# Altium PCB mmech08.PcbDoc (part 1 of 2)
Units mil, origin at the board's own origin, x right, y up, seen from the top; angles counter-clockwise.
Board outline 2098.43 x 3200 mil, 4 copper layers (Top Layer, Ground Plane, Mid Layer 1, Bottom Layer), stack 59.851 mil thick; 121 components, 87 nets, 440 pads, 296 vias.
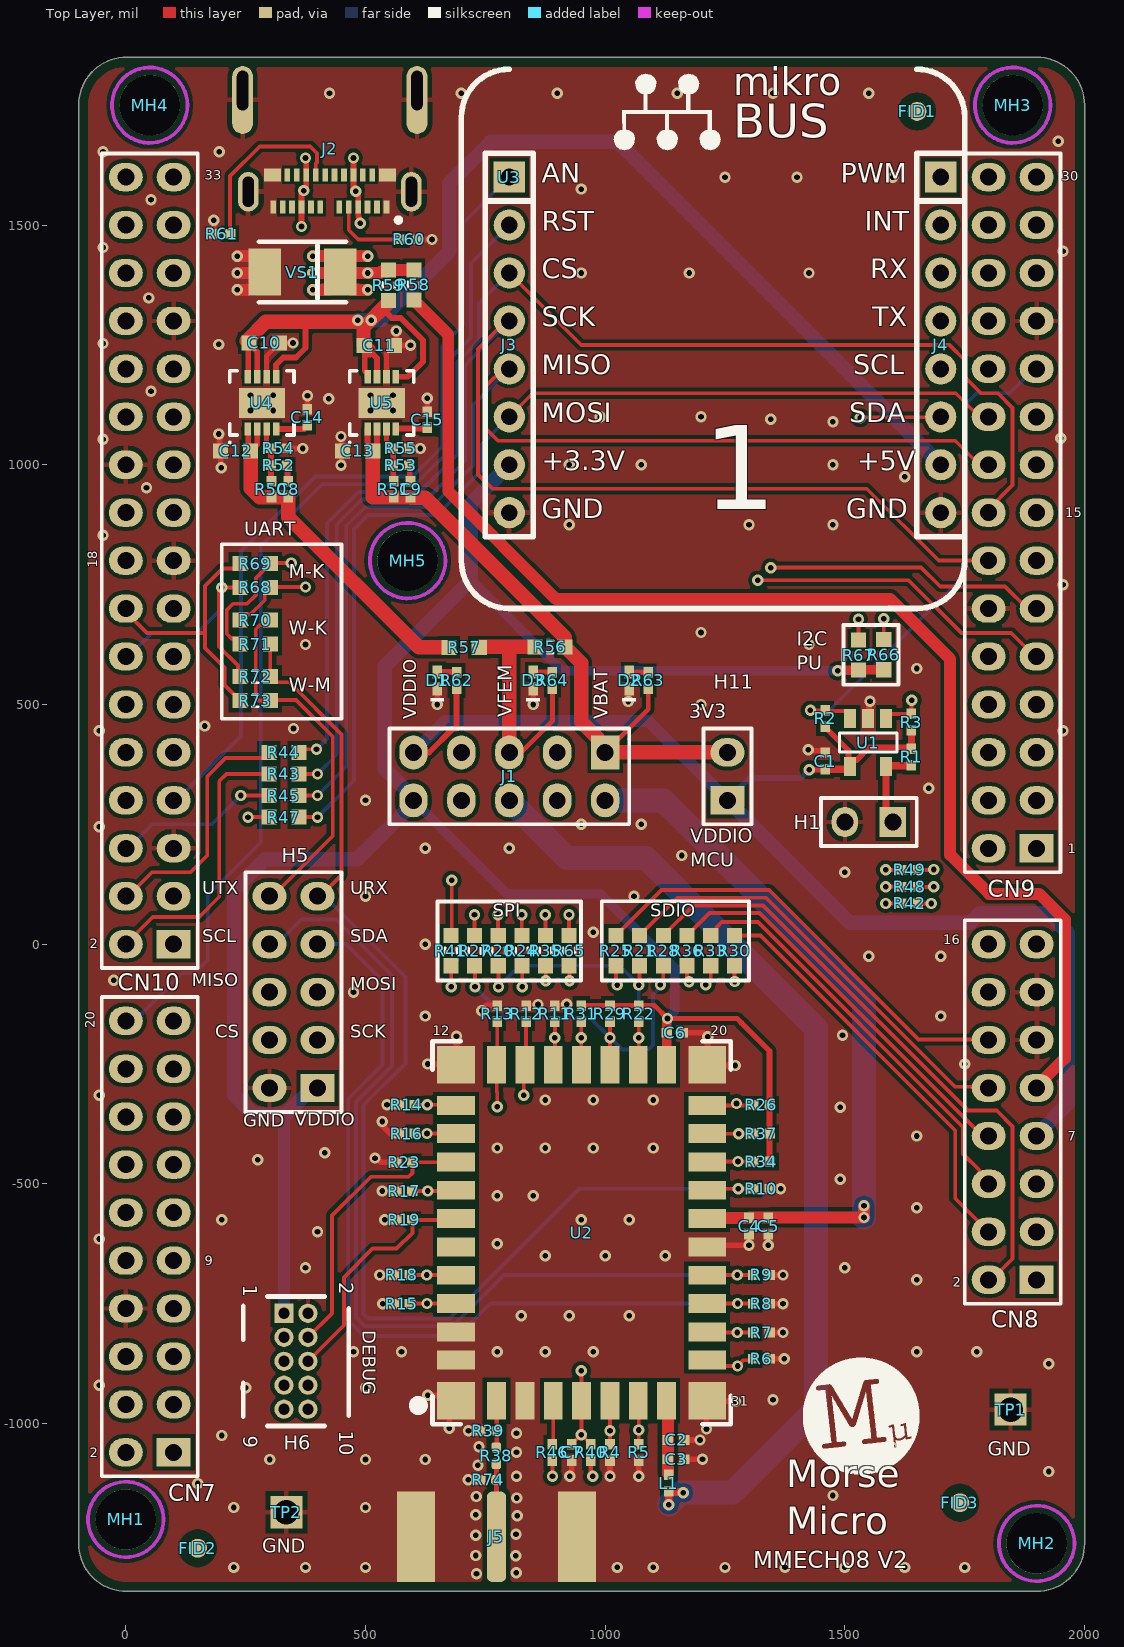
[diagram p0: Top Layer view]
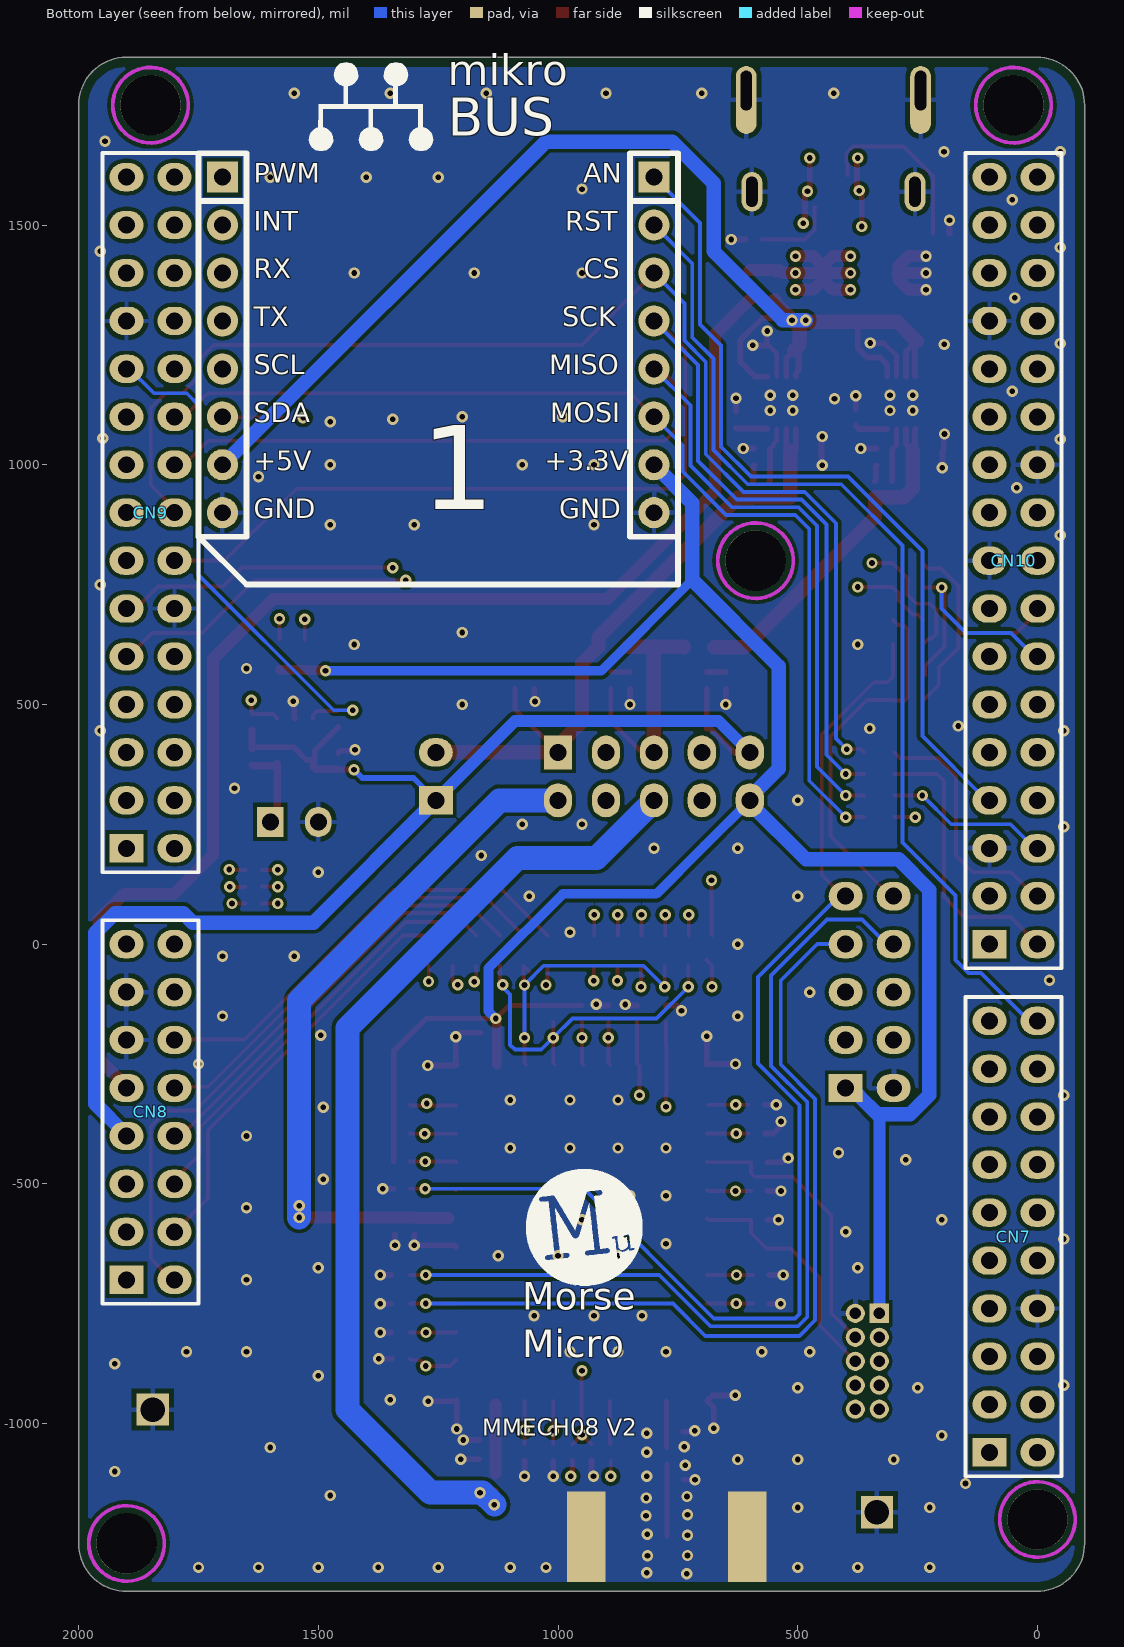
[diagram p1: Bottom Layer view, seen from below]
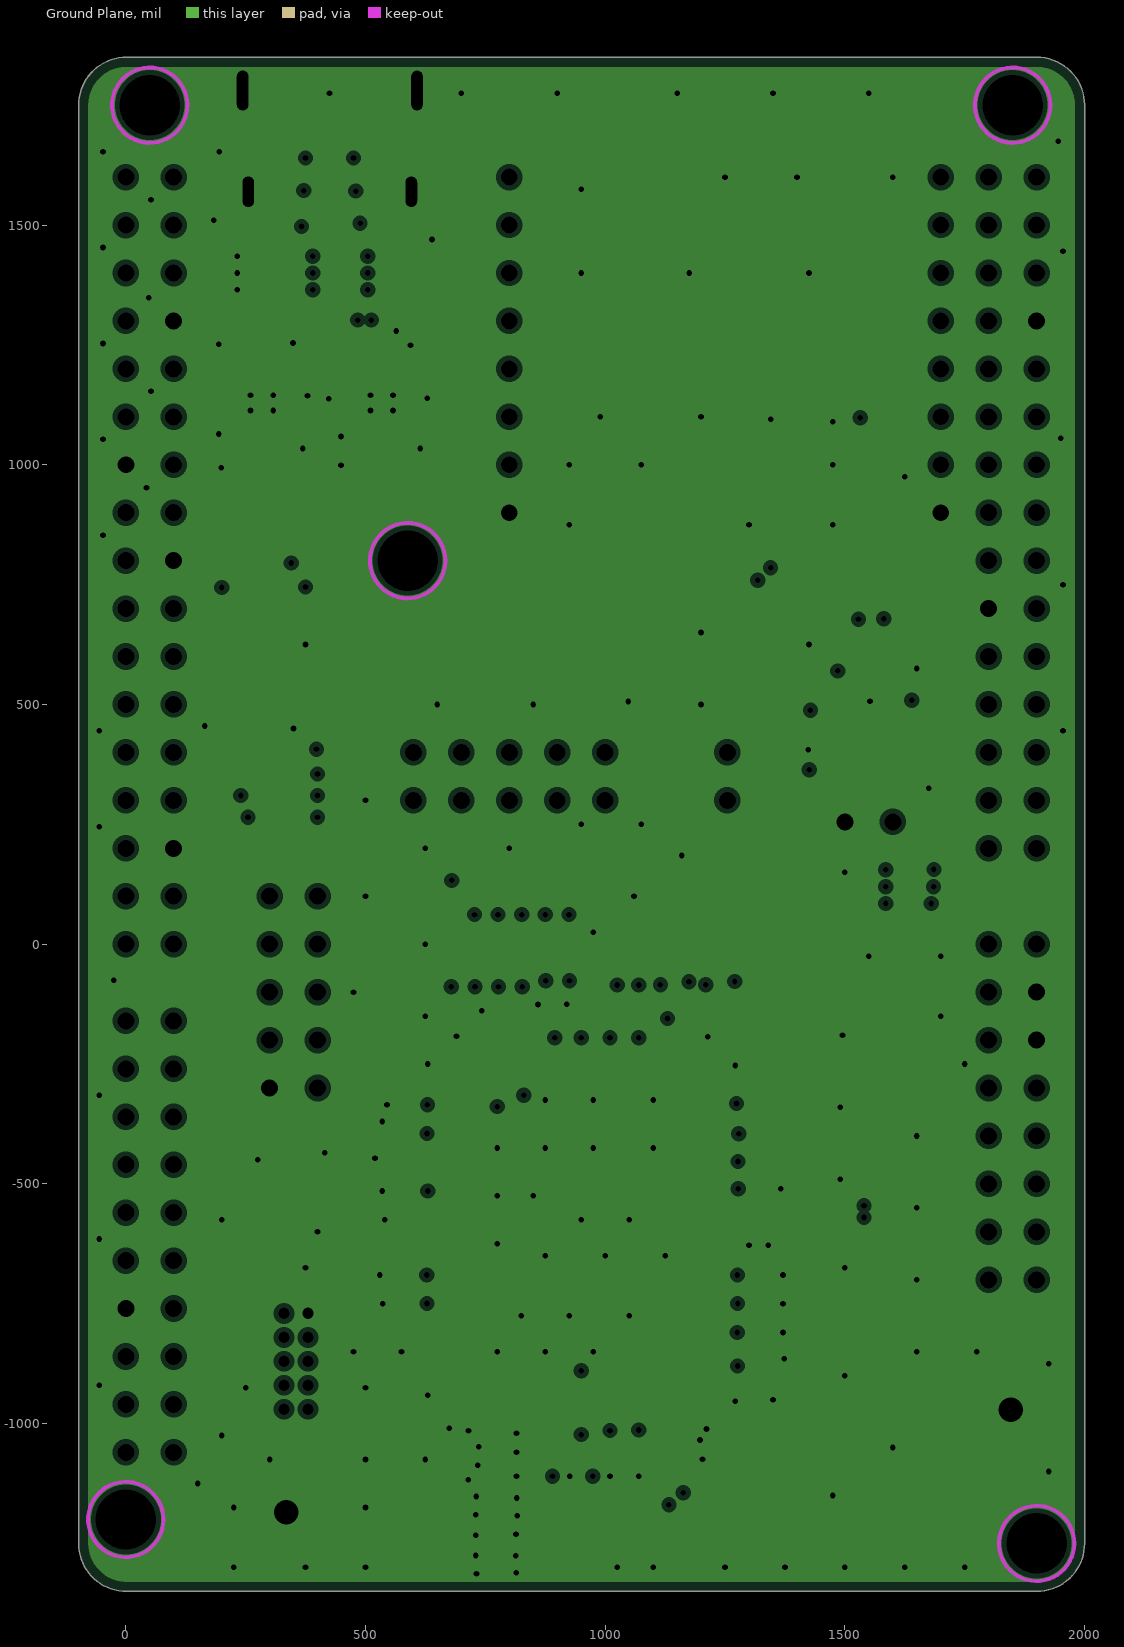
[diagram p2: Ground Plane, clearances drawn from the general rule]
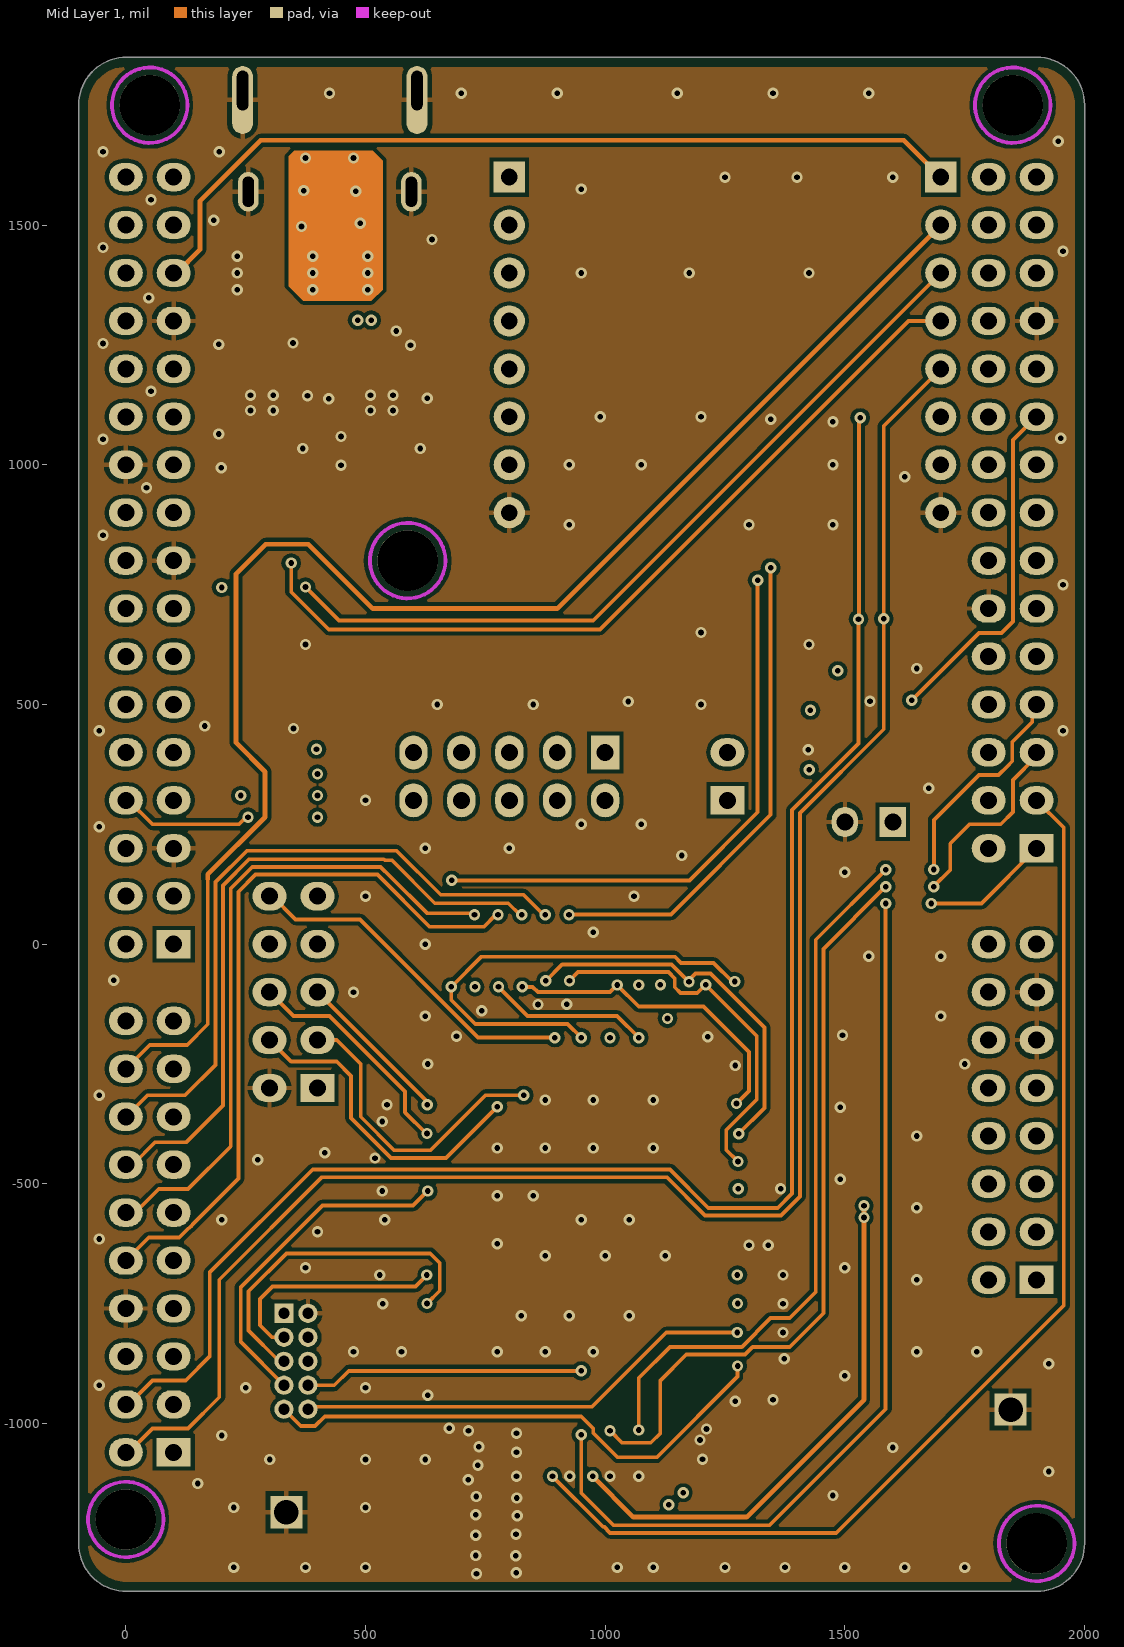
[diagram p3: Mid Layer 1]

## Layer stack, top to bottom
Top Solder: solder mask 0.787, SM-001, Dk 4.2
Top Layer: signal copper 1.378
Dielectric 1: prepreg 6.5, PP, Dk 4.29
Ground Plane: plane copper 1.378, net GND
Dielectric 2: core 41.3386, Core, Dk 4.29
Mid Layer 1: signal copper 1.378
Dielectric 3: prepreg 6.5, PP, Dk 4.29
Bottom Layer: signal copper 1.378
Bottom Solder: solder mask 0.787, SM-001, Dk 4.2

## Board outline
-98.37,-1250 -98.37,1750 cw(c1.63,1750) 1.63,1850 1900.05,1850 cw(c1900.05,1750) 2000.05,1750 2000.05,-1250 2000.02,-1250 cw(c1900.02,-1250) 1900.02,-1350 1.63,-1350 cw(c1.63,-1250)

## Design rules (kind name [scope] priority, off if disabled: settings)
AssemblyTestPointUsage [All] p1 off:
AssemblyTestpoint [All] p1 off: testpointundercomponent=TRUE minsize=40 maxsize=100 preferedsize=60 minholesize=0 maxholesize=40 preferedholesize=32 testpointgrid=1 usegrid=TRUE gridtolerance=0.01 allowsidetop=TRUE allowsidebottom=TRUE
BoardOutlineClearance [(not OnTopSilkscreen) AND (NOT OnBottomSilkscreen) and (not OnMultiLayer) and (not IsText)] p1: gap=20 ignorepadtopadclearanceinfootprint=FALSE
Clearance "RF Clearance" [InNetClass('RF-Net') vs InPolygon] p1: gap=10 ignorepadtopadclearanceinfootprint=TRUE
Clearance "Schematic Clearance Constraint_2" [InComponent('FID3')] p2: gap=0 ignorepadtopadclearanceinfootprint=FALSE
Clearance "Schematic Clearance Constraint_1" [InComponent('FID2')] p3: gap=0 ignorepadtopadclearanceinfootprint=FALSE
Clearance "Schematic Clearance Constraint" [InComponent('FID1')] p4: gap=0 ignorepadtopadclearanceinfootprint=FALSE
Clearance Clearance_U4_U5_J2 [InComponent('J2','U4','U5')] p5: gap=6 ignorepadtopadclearanceinfootprint=TRUE
Clearance [All] p6: gap=8 ignorepadtopadclearanceinfootprint=TRUE
ComponentClearance [All] p1 off: gap=10 collisioncheckmode=3 verticalgap=10 showdistances=FALSE
DiffPairsRouting [All] p1 off: maxlimit=10 minlimit=10 mostfreqgap=10 toplayer_minwidth=15 toplayer_maxwidth=15 toplayer_prefwidth=15 midlayer3_minwidth=15 midlayer3_maxwidth=15 midlayer3_prefwidth=15 bottomlayer_minwidth=15 bottomlayer_maxwidth=15 bottomlayer_prefwidth=15 maxuncoupledlength=500
FabricationTestPointUsage [All] p1 off: valid=0 allowmultiple=FALSE
FabricationTestpoint [All] p1 off: side=3 testpointundercomponent=TRUE minsize=40 maxsize=100 preferedsize=60 minholesize=0 maxholesize=40 preferedholesize=32 testpointgrid=1 allowsidetop=TRUE allowsidebottom=TRUE usegrid=TRUE gridtolerance=0.01
FanoutControl Fanout_BGA [IsBGA] p1 off: bgadir=Out bgaviamode=Centered fanoutstyle=Auto fanoutdirection=Alternating viagrid=1 // Fanout_BGA (Default Rule)
FanoutControl Fanout_LCC [IsLCC] p2 off: bgadir=Out bgaviamode=Centered fanoutstyle=Auto fanoutdirection=Alternating viagrid=1 // Fanout_LCC (Default Rule)
FanoutControl Fanout_SOIC [IsSOIC] p3 off: bgadir=Out bgaviamode=Centered fanoutstyle=Auto fanoutdirection=Alternating viagrid=1 // Fanout_SOIC (Default Rule)
FanoutControl Fanout_Small [(CompPinCount < 5)] p4 off: bgadir=Out bgaviamode=Centered fanoutstyle=Auto fanoutdirection=OutThenIn viagrid=1 // Fanout_Small (Default Rule)
FanoutControl Fanout_Default [All] p5 off: bgadir=Out bgaviamode=Centered fanoutstyle=Auto fanoutdirection=Alternating viagrid=1 // Fanout_Default (Default Rule)
Height TP1 [InComponent('TP1')] p1: minheight=0 maxheight=472.44 prefheight=118.11
Height "POGO Pins" [InComponentClass('POGO')] p2: minheight=0 maxheight=275.59 prefheight=196.85
Height "Under Socket" [WithinRoom('ROOM_SOCKET')] p3: minheight=0 maxheight=157.48 prefheight=118.11
Height [All] p4 off: minheight=0 maxheight=1000 prefheight=500
HoleSize [All] p1: absolutevalues=TRUE maxlimit=200 minlimit=8 maxpercent=80.000 minpercent=20.000
HoleToHoleClearance [All] p1: gap=8 allowstackedmicrovias=TRUE
LayerPairs [All] p1 off: enforce=TRUE
MatchedLengths MatchLengths_U1_Passives_J5_1 [InxSignalClass('xSignals_U1_Passives_J5_MatchLengthsClass_1')] p1: tolerance=50 checknetsindiffpair=FALSE checkdiffpairvsdiffpair=TRUE checkxsignals=TRUE checkothers=TRUE
MatchedLengths MatchLengths_U1_Passives_J5 [InxSignalClass('xSignals_U1_Passives_J5_MatchLengthsClass')] p2: tolerance=50 checknetsindiffpair=FALSE checkdiffpairvsdiffpair=TRUE checkxsignals=TRUE checkothers=TRUE
MinimumSolderMaskSliver [not InComponent('U4','U1','U5','U6','U7','U8','U9','U10')] p1: minsoldermaskwidth=3
PlaneClearance [All] p1: clearance=10
PlaneConnect [All] p1: pad.planeconnectstyle=Relief pad.reliefexpansion=20 pad.reliefentries=4 pad.reliefconductorwidth=10 pad.reliefairgap=10 via.planeconnectstyle=Direct via.reliefexpansion=20 via.reliefentries=4 via.reliefconductorwidth=10 via.reliefairgap=10
PolygonConnect "Schematic Polygon Connect Style" [InComponent('J5')] p1: connectstyle=Direct reliefconductorwidth=10 reliefentries=4 polygonreliefangle="45 Angle" airgapwidth=10
PolygonConnect [All] p2: thpad.connectstyle=Relief thpad.reliefconductorwidth=10 thpad.reliefentries=4 thpad.polygonreliefangle="90 Angle" thpad.airgapwidth=10 smdpad.connectstyle=Direct smdpad.reliefconductorwidth=10 smdpad.reliefentries=4 smdpad.polygonreliefangle="90 Angle" smdpad.airgapwidth=10 via.connectstyle=Direct via.reliefconductorwidth=10 via.reliefentries=4 via.polygonreliefangle="90 Angle" via.airgapwidth=10
RoutingVias [All] p1: holewidth=8 width=20 viastyle="Through Hole" minholewidth=8 minwidth=20 maxholewidth=28 maxwidth=50
SilkToSilkClearance [All] p1 off: silktosilkclearance=8
SilkToSolderMaskClearance [IsPad] p1 off: minsilkscreentomaskgap=4 clearancetoexposedcopper=TRUE
SolderMaskExpansion [All] p1: expansion=4 istentingtop=FALSE
SupplyNets SupplyNets_1 [InNet('VDD33')] p1: voltage=3.300
SupplyNets SupplyNets_2 [InNet('VBAT')] p2: voltage=3.300
SupplyNets SupplyNets_3 [InNet('VDD5')] p3: voltage=5.000
SupplyNets SupplyNets_4 [InNet('VDD5_RPi')] p4: voltage=5.000
SupplyNets SupplyNets_5 [InNet('VDD_FEM')] p5: voltage=4.000
SupplyNets SupplyNets_6 [InNet('VDD_LNA')] p6: voltage=4.000
SupplyNets SupplyNets_7 [InNet('VDD_PA')] p7: voltage=4.000
SupplyNets [InNet('GND')] p8: voltage=0.000
UnConnectedPin [All] p1 off:
UnRoutedNet [All] p1: checkbadconnections=TRUE
Width [All] p1: maxlimit=50 minlimit=8 preferedwidth=8
Width "RF Width" [InNetClass('RF-Net')] p2: maxlimit=50 minlimit=7 preferedwidth=8 toplayer_maxwidth=7 toplayer_prefwidth=10 impedanceprofiledriven=TRUE impedanceprofileid={2BAD1660-FF1E-4629-AB45-93BC2CD73358} impedanceprofilevalue=50.000000 minimp=50.000000 maximp=50.000000 favimp=50.000000
9 further rules are at their usual default settings.

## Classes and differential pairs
net class RF-Net: NetJ5_1 NetR38_1
component class CHIP_OTHER: C10 C11 C12 C13 D1 D2 D3 R20 R21 R24 R25 R27 R28 R30 R33 R35 R36 R41 R43 R44 R45 R47 R56 R57 R58 R59 R65 R66 R67 R68 R69 R70 R71 R72 R73
component class MMECH08_Power: C8 C9 C10 C11 C12 C13 C14 C15 D1 D2 D3 FID1 FID2 FID3 H11 J1 J2 MH1 MH2 MH3 MH4 MH5 R50 R51 R52 R53 R54 R55 R56 R57 R58 R59 R60 R61 R62 R63 R64 TP1 TP2 U4 U5 VS1
component class CHIP_MICRO: C1 C2 C3 C4 C5 C6 C7 C8 C9 C14 C15 L1 R1 R2 R3 R4 R5 R6 R7 R8 R9 R10 R11 R12 R13 R14 R15 R16 R17 R18 R19 R22 R23 R26 R29 R31 R34 R37 R38 R39 R40 R42 R46 R48 R49 R50 R51 R52 R53 R54 R55 R60 R61 R62 R63 R64 R74
component class MMECH08_Module_Interfaces: C1 C2 C3 C4 C5 C6 C7 CN7 CN8 CN9 CN10 H1 H5 H6 J3 J4 J5 L1 R1 R2 R3 R4 R5 R6 R7 R8 R9 R10 R11 R12 R13 R14 R15 R16 R17 R18 R19 R20 R21 R22 R23 R24 R25 R26 R27 R28 R29 R30 R31 R33 R34 R35 R36 R37 R38 R39 R40 R41 R42 R43 R44 R45 R46 R47 R48 R49 R65 R66 R67 R68 R69 R70 R71 R72 R73 R74 U1 U2 U3
component class PCB_PATTERN: FID1 FID2 FID3 FID7 FID8 MH1 MH2 MH3 MH4 MH5
component class COMP_OTHER: CN7 CN8 CN9 CN10 H1 H5 H6 H11 J1 J2 J3 J4 J5 TP1 TP2 U1 U2 U3 U4 U5 VS1

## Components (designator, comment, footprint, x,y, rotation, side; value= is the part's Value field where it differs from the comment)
C1 "CAP" 0402_CAP 1458.63,382 r90 top value=100nF
C2 "CAP" 0402_CAP 1147.84,-1034.16 r0 top value=100nF
C3 "CAP" 0402_CAP 1147.84,-1074.16 r0 top value=10uF
C4 "CAP" 0402_CAP 1300,-588 r90 top value=100nF
C5 "CAP" 0402_CAP 1340,-588 r270 top value=10uF
C6 "CAP" 0402_CAP 1145,-185 r0 top value=100nF
C7 "CAP" 0402_CAP 930,-1060 r270 top value=2.2uF
C8 "CAP_DNF" 0402_cap_dnf 338.94,949 r90 top value=DNF
C9 "CAP_DNF" 0402_cap_dnf 593.94,949 r90 top value=DNF
C10 "CAP" 0603_cap 288.94,1254 r0 top value=10uF
C11 "CAP" 0603_cap 528.88,1249 r0 top value=10uF
C12 "CAP" 0603_cap 228.94,1029 r180 top value=10uF
C13 "CAP" 0603_cap 483.94,1029 r180 top value=10uF
C14 "CAP" 0402_cap 378.94,1099 r90 top value=1nF
C15 "CAP" 0402_cap 628.95,1094 r90 top value=1nF
CN7 ".Designator" HDR2X10 100,-1060 r90 bottom
CN8 ".Designator" HDR2X8 1900,-700 r90 bottom
CN9 ".Designator" HDR2X15 1900,200 r90 bottom
CN10 ".Designator" HDR2X17 100,0 r90 bottom
D1 "LED_G" LED_0402_GREEN 650,550 r270 top value=Green
D2 "LED_G" LED_0402_GREEN 1050,550 r270 top value=Green
D3 "LED_G" LED_0402_GREEN 850,550 r270 top value=Green
FID1 "FIDUCIAL" FIDUCIAL_1MM 1650.63,1737 r0 top
FID2 "FIDUCIAL" FIDUCIAL_1MM 150,-1260 r0 top
FID3 "FIDUCIAL" FIDUCIAL_1MM 1740,-1165 r90 top
H1 "HDR_1X2_DNF" HDR1X2_DNF 1600,255 r180 top
H5 "HDR_2X5" HDR2X5 400,-300 r90 top
H6 "2X5_FTSH_DV_K" FTSH_105_D_K 355,-870 r270 top
H11 "HDR_1X2" HDR1X2 1255,300 r90 top
J1 "HDR_2X5" HDR2X5 1000,400 r180 top
J2 "CONN RCP USB3.1 TYPEC 24P SMD RA" USB-C_RCP 425.63,1659 r180 top
J3 "75915-308LF * 2" 75915-308LF 800,1600 r0 top
J4 "75915-308LF" 75915-308LF 1700,1600 r0 top
J5 "SMA-EDGE" SMA_RA-EDGE 773.27,-1350 r0 top
L1 "IND" 0402_ind 1132.84,-1124.16 r270 top value="60 Ohms @ 100MHz"
MH1 "MH_360_320_NPTH" MH_360_320_NPTH 0.02,-1200 r0 top locked
MH2 "MH_360_320_NPTH" MH_360_320_NPTH 1900.02,-1250 r0 top locked
MH3 "MH_360_320_NPTH" MH_360_320_NPTH 1850.02,1750 r0 top locked
MH4 "MH_360_320_NPTH" MH_360_320_NPTH 50.02,1750 r0 top locked
MH5 "MH_360_320_NPTH" MH_360_320_NPTH 588.02,800 r0 top locked
R1 "RES" 0402_RES#1 1638.63,390.63 r270 top value=1K
R2 "RES" 0402_RES#1 1458.63,471 r90 top value=3k9
R3 "RES" 0402_RES#1 1638.63,463.16 r90 top value=3k9
R4 "RES" 0402_RES#1 1010,-1060 r270 top value=10K
R5 "RES" 0402_res 1070,-1060 r270 top value=10K
R6 "RES" 0402_RES#1 1325.84,-865 r0 top value=10K
R7 "RES" 0402_RES#1 1325.84,-810 r0 top value=10K
R8 "RES" 0402_RES#1 1325.84,-750 r0 top value=10K
R9 "RES" 0402_RES#1 1325.84,-690 r0 top value=10K
R10 "RES" 0402_RES#1 1325.84,-510 r0 top value=10K
R11 "RES" 0402_RES#1 895,-145 r90 top value=10K
R12 "RES" 0402_RES#1 835,-145 r90 top value=10K
R13 "RES" 0402_RES#1 775,-145 r90 top value=10K
R14 "RES" 0402_RES#1 585.84,-335 r180 top value=10K
R15 "RES" 0402_RES#1 575.84,-750 r180 top value=10K
R16 "RES" 0402_RES#1 585.84,-395 r180 top value=10K
R17 "RES_DNF" 0402_res_dnf#1 580.84,-515 r180 top value=DNF
R18 "RES" 0402_RES#1 575.84,-690 r180 top value=10K
R19 "RES" 0402_RES#1 580.84,-575 r180 top value=10K
R20 "RES" 0603_res 776.91,-13.5 r270 top value=0R
R21 "RES_DNF" 0603_res_dnf 1071.75,-13.5 r90 top value=DNF
R22 "RES" 0402_RES#1 1070,-145 r270 top value=47k
R23 "RES" 0402_RES#1 580.84,-455 r180 top value=10K
R24 "RES" 0603_res 826.2,-13.5 r270 top value=0R
R25 "RES_DNF" 0603_res_dnf 1022.28,-13.5 r90 top value=DNF
R26 "RES" 0402_RES#1 1325.84,-335 r180 top value=47k
R27 "RES" 0603_res 727.61,-13.5 r270 top value=0R
R28 "RES_DNF" 0603_res_dnf 1121.22,-13.5 r90 top value=DNF
R29 "RES" 0402_RES#1 1010,-145 r90 top value=47k
R30 "RES_DNF" 0603_res_dnf 1269.63,-13.5 r90 top value=DNF
R31 "RES" 0402_RES#1 950,-145 r90 top value=47k
R33 "RES_DNF" 0603_res_dnf 1220.16,-13.5 r90 top value=DNF
R34 "RES" 0402_RES#1 1325.84,-453.39 r0 top value=47k
R35 "RES" 0603_res 875.5,-13.5 r270 top value=0R
R36 "RES_DNF" 0603_res_dnf 1170.69,-13.5 r90 top value=DNF
R37 "RES" 0402_RES#1 1325.84,-395 r180 top value=47k
R38 "RES" 0402_RES#2 773,-1067 r270 top value=0R
R39 "RES_DNF" 0402_res_dnf#2 756.13,-1015.12 r180 top value=DNF
R40 "RES" 0402_RES#1 970,-1060 r90 top value=220k
R41 "RES" 0603_res 678.32,-13.5 r270 top value=0R
R42 "RES" 0402_res 1635,85 r0 top value=0R
R43 "RES_DNF" 0603_res_dnf 330,355 r0 top value=DNF
R44 "RES_DNF" 0603_res_dnf 330,400 r0 top value=DNF
R45 "RES_DNF" 0603_res_dnf 330,310 r0 top value=DNF
R46 "RES" 0402_res 890,-1060 r270 top value=10K
R47 "RES_DNF" 0603_res_dnf 330,265 r0 top value=DNF
R48 "RES" 0402_res 1635,120 r0 top value=0R
R49 "RES" 0402_res 1635,155 r0 top value=0R
R50 "RES" 0402_res 303.94,949 r90 top value=1k
R51 "RES" 0402_res 558.94,949 r90 top value=1k
R52 "RES_DNF" 0402_res_dnf#1 318.94,999 r0 top value=DNF
R53 "RES_DNF" 0402_res_dnf#1 573.94,999 r0 top value=DNF
R54 "RES" 0402_res 318.94,1034 r0 top value=10k
R55 "RES" 0402_res 573.94,1034 r0 top value=10k
R56 "RES" 0603_res 885,620 r180 top value=0R
R57 "RES_DNF" 0603_res_dnf 705.75,619.17 r0 top value=DNF
R58 "RES" 0603_res 600.83,1375.09 r270 top value=0R
R59 "RES" 0603_res 548.29,1374.35 r270 top value=0R
R60 "RES" 0402_RES#1 591.63,1470 r0 top value=5K1
R61 "RES" 0402_RES#1 200.63,1482 r180 top value=5K1
R62 "RES" 0402_RES#1 690,550 r270 top value=330R
R63 "RES" 0402_RES#1 1090,550 r270 top value=330R
R64 "RES" 0402_res 890,550 r270 top value=330R
R65 "RES" 0603_res 924.79,-13.5 r270 top value=0R
R66 "RES_DNF" 0603_res_dnf 1581,604 r90 top value=DNF
R67 "RES_DNF" 0603_res_dnf 1528.47,603.07 r90 top value=DNF
R68 "RES_DNF" 0603_res_dnf 270,744 r180 top value=DNF
R69 "RES_DNF" 0603_res_dnf 270,794 r180 top value=DNF
R70 "RES_DNF" 0603_res_dnf 270,676 r0 top value=DNF
R71 "RES_DNF" 0603_res_dnf 270,626 r0 top value=DNF
R72 "RES" 0603_res 270,558 r0 top value=0R
R73 "RES" 0603_res 270,508 r0 top value=0R
R74 "RES_DNF" 0402_res_dnf#2 756.13,-1117.12 r180 top value=DNF
TP1 "TP-BLK" TP-100_BLACK 1845.47,-970.93 r0 top
TP2 "TP-BLK" TP-100_BLACK 335,-1185 r0 top
U1 "AT24C32D" SOT-23_5 1548.63,420.63 r270 top
U2 "MM61xx-MF04151" MF04 950.84,-601.97 r90 top locked
U3 "MIKROBUS_Host" MIKROBUS_Host_SD 800,1600 r0 top value="MIKROBUS Host"
U4 "ADM7172" PSON50P300X80_HS-9N 283.94,1129 r90 top
U5 "ADM7172" PSON50P300X80_HS-9N 533.94,1129 r90 top
VS1 "Varistor_Uni" DO-214AC 368.63,1402 r0 top value=6V

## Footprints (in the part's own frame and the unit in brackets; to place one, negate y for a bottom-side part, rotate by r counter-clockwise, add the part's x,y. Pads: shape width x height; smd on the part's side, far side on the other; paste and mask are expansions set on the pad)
0402_CAP [mil]
  rect 22x20 smd: 1(-17,0) 2(17,0)
  body extent -21,-11 21,11, height 22
0402_cap [mil]
  rect 22x20 smd: 1(-17,0) 2(17,0)
  body extent -21,-11 21,11, height 22
0402_cap_dnf [mil]
  rect 22x20 smd paste-196.85: 1(-17,0) 2(17,0)
  body extent -20,-10 20,10, height 20
0402_ind [mil]
  rect 22x20 smd: 1(-17,0) 2(17,0)
  body extent -22,-12 22,12, height 20
0402_RES#1 [mil]
  rect 22x20 smd: 1(-17,0) 2(17,0)
  body extent -21,-11 21,11, height 16
0402_RES#2 [mil]
  rrect50% 22x20 smd: 1(-17,0) 2(17,0)
  body extent -21,-11 21,11, height 16
0402_res [mil]
  rect 22x20 smd: 1(-17,0) 2(17,0)
  body extent -21,-11 21,11, height 16
0402_res_dnf#1 [mil]
  rect 22x20 smd paste-196.85: 1(-17,0) 2(17,0)
  body extent -20,-10 20,10, height 20
0402_res_dnf#2 [mil]
  rrect50% 22x20 smd paste-196.85: 1(-17,0)
  rect 22x20 smd paste-196.85: 2(17,0)
  body extent -20,-10 20,10, height 20
0603_cap [mm]
  rect 0.8x0.8 smd: 1(-0.8,0) 2(0.8,0)
  body extent -0.85,-0.45 0.85,0.45, height 0.9
0603_res [mm]
  rect 0.8x0.8 smd: 1(-0.8,0) 2(0.8,0)
  silkscreen extent -0.15,-0.33 0.15,0.33, body extent -0.82,-0.48 0.82,0.48, height 0.55
0603_res_dnf [mm]
  rect 0.8x0.8 smd paste-10: 1(-0.8,0) 2(0.8,0)
  body extent -0.8,-0.4 0.8,0.4, height 0
75915-308LF [mil] "CONN RCPT 8POS 0.1 GOLD PCB"
  rect 65x65 hole 35: 1(0,0)
  round 65 hole 35: 2(0,-100) 3(0,-200) 4(0,-300) 5(0,-400) 6(0,-500) 7(0,-600) 8(0,-700)
  silkscreen extent -50,-750 50,50, body extent -49,-755 49,55, height 335
DO-214AC [mm]
  rect 1.7x2.5 smd: A(-2,0) K(2,0)
  silkscreen extent -2.3,-1.6 2.3,1.6, body extent -2.6,-1.4 2.6,1.4, height 2.3
FIDUCIAL_1MM [mm]
  round 1 smd paste-1 mask+0.5: 1(0,0)
  Top Layer pour cut-out: -1,0 -0.924,-0.383 -0.707,-0.707 -0.383,-0.924 0,-1 0,-1 0.383,-0.924 0.707,-0.707 0.924,-0.383 1,0 1,0 0.924,0.383 0.707,0.707 0.383,0.924 0,1 0,1 -0.383,0.924 -0.707,0.707 -0.924,0.383 -1,0
FTSH_105_D_K [mil]
  rect 40x40 hole 23.62 mask+3: 1(-100,-25)
  round 40 hole 23.62 mask+3: 2(-100,25) 3(-50,-25) 4(-50,25) 5(0,-25) 6(0,25) 7(50,-25) 8(50,25) 9(100,-25) 10(100,25)
  silkscreen extent -135,-110 135,110, body extent -124,-100 123,100, height 225
HDR1X2 [mm] "Connector; Header; 2 Position"
  rect 1.5x1.8 hole 0.9: 1(0,0)
  oval 1.5x1.8 hole 0.9: 2(2.54,0)
  silkscreen extent -1.27,-1.27 3.81,1.27, body extent -1.27,-1.22 3.81,1.22, height 10.3
HDR1X2_DNF [mm] "Connector; Header; 2 Position"
  rect 1.4x1.6 hole 0.9: 1(0,0)
  oval 1.4x1.6 hole 0.9: 2(2.54,0)
  silkscreen extent -1.27,-1.27 3.81,1.27, body extent -1.27,-1.27 3.81,1.27, height 0.01
HDR2X5 [mm] "Connector; Header; 5x2 Position"
  rect 1.5x1.8 hole 0.9: 1(0,0)
  oval 1.5x1.8 hole 0.9: 2(0,2.54) 3(2.54,0) 4(2.54,2.54) 5(5.08,0) 6(5.08,2.54) 7(7.62,0) 8(7.62,2.54) 9(10.16,0) 10(10.16,2.54)
  silkscreen extent -1.27,-1.27 11.43,3.81, body extent -1.27,-1.27 11.43,3.81, height 9
HDR2X8 [mm] "Connector; Header; 8x2 Position"
  rect 1.5x1.8 hole 0.9: 1(0,0)
  oval 1.5x1.8 hole 0.9: 2(0,-2.54) 3(2.54,0) 4(2.54,-2.54) 5(5.08,0) 6(5.08,-2.54) 7(7.62,0) 8(7.62,-2.54) 9(10.16,0) 10(10.16,-2.54) 11(12.7,0) 12(12.7,-2.54) 13(15.24,0) 14(15.24,-2.54) 15(17.78,0) 16(17.78,-2.54)
  silkscreen extent -1.27,-3.81 19.05,1.27, body extent -1.27,-3.81 19.05,1.27, height 9
HDR2X10 [mm] "Connector; Header; 10x2 Position"
  rect 1.5x1.8 hole 0.9: 1(0,0)
  oval 1.5x1.8 hole 0.9: 2(0,-2.54) 3(2.54,0) 4(2.54,-2.54) 5(5.08,0) 6(5.08,-2.54) 7(7.62,0) 8(7.62,-2.54) 9(10.16,0) 10(10.16,-2.54) 11(12.7,0) 12(12.7,-2.54) 13(15.24,0) 14(15.24,-2.54) 15(17.78,0) 16(17.78,-2.54) 17(20.32,0) 18(20.32,-2.54) 19(22.86,0) 20(22.86,-2.54)
  silkscreen extent -1.27,-3.81 24.13,1.27, body extent -1.27,-3.81 24.13,1.27, height 9
HDR2X15 [mm] "Connector; Header; 15x2 Position"
  rect 1.5x1.8 hole 0.9: 1(0,0)
  oval 1.5x1.8 hole 0.9: 2(0,-2.54) 3(2.54,0) 4(2.54,-2.54) 5(5.08,0) 6(5.08,-2.54) 7(7.62,0) 8(7.62,-2.54) 9(10.16,0) 10(10.16,-2.54) 11(12.7,0) 12(12.7,-2.54) 13(15.24,0) 14(15.24,-2.54) 15(17.78,0) 16(17.78,-2.54) 17(20.32,0) 18(20.32,-2.54) 19(22.86,0) 20(22.86,-2.54) 21(25.4,0) 22(25.4,-2.54) 23(27.94,0) 24(27.94,-2.54) 25(30.48,0) 26(30.48,-2.54) 27(33.02,0) 28(33.02,-2.54) 29(35.56,0) 30(35.56,-2.54)
  silkscreen extent -1.27,-3.81 36.83,1.27, body extent -1.27,-3.81 36.83,1.27, height 9
HDR2X17 [mm] "Connector; Header; 17x2 Position"
  rect 1.5x1.8 hole 0.9: 1(0,0)
  oval 1.5x1.8 hole 0.9: 2(0,-2.54) 3(2.54,0) 4(2.54,-2.54) 5(5.08,0) 6(5.08,-2.54) 7(7.62,0) 8(7.62,-2.54) 9(10.16,0) 10(10.16,-2.54) 11(12.7,0) 12(12.7,-2.54) 13(15.24,0) 14(15.24,-2.54) 15(17.78,0) 16(17.78,-2.54) 17(20.32,0) 18(20.32,-2.54) 19(22.86,0) 20(22.86,-2.54) 21(25.4,0) 22(25.4,-2.54) 23(27.94,0) 24(27.94,-2.54) 25(30.48,0) 26(30.48,-2.54) 27(33.02,0) 28(33.02,-2.54) 29(35.56,0) 30(35.56,-2.54) 31(38.1,0) 32(38.1,-2.54) 33(40.64,0) 34(40.64,-2.54)
  silkscreen extent -1.27,-3.81 41.91,1.27, body extent -1.27,-3.81 41.91,1.27, height 9
LED_0402_GREEN [mm]
  rect 0.7x0.5 smd: A(-0.45,0) K(0.45,0)
  silkscreen extent 0.93,-0.38 1.1,0.35, body extent -0.5,-0.25 0.5,0.25, height 0.51
MF04 [mm]
  rect 2x2 smd: 1(-8.9,6.65) 12(8.9,6.65) 20(8.9,-6.65) 31(-8.9,-6.65)
  rect 1x2 smd: 2(-6.75,6.65) 3(-5.25,6.65) 4(-3.75,6.65) 5(-2.25,6.65) 6(-0.75,6.65) 7(0.75,6.65) 8(2.25,6.65) 9(3.75,6.65) 10(5.25,6.65) 11(6.75,6.65) 21(6.75,-6.65) 22(5.25,-6.65) 23(3.75,-6.65) 24(2.25,-6.65) 25(0.75,-6.65) 26(-0.75,-6.65) 27(-2.25,-6.65) 28(-3.75,-6.65) 29(-5.25,-6.65) 30(-6.75,-6.65)
  rect 2x1 smd: 13(8.9,4.5) 14(8.9,3) 15(8.9,1.5) 16(8.9,0) 17(8.9,-1.5) 18(8.9,-3) 19(8.9,-4.5) 32(-8.9,-4.5) 33(-8.9,-3) 34(-8.9,-1.5) 35(-8.9,0) 36(-8.9,1.5) 37(-8.9,3) 38(-8.9,4.5)
  silkscreen extent -10.15,-7.9 10.15,8.9, body extent -9.25,-7 9.25,7, height 1.9
MH_360_320_NPTH [mm] "Non-plated mount hole 3.2mm hole 3.60mm diameter"
  round 3.2 hole 3.2 unplated mask+0.25: 1(0,0)
  Keep-Out Layer circle w0.2: c0,0 r2
MIKROBUS_Host_SD [mil] "MIKROBUS HOST SOCKET"
  silkscreen extent -100,-900 950,225, body extent -49,-755 949,55, height 335
PSON50P300X80_HS-9N [mm] "PSON, 8-Leads, Body 3.00x3.00mm, Pitch 0.50mm, Thermal Pad 2.44x1.60mm, IPC Medium Density"
  rect 0.7x0.35 smd mask+0.076: 1(-1.385,0.75) 2(-1.385,0.25) 3(-1.385,-0.25) 4(-1.385,-0.75) 5(1.385,-0.75) 6(1.385,-0.25) 7(1.385,0.25) 8(1.385,0.75)
  rect 1.6x2.44 smd mask+0.076: EP(0,0)
  silkscreen extent -2.15,-1.7 1.7,1.75, body extent -1.55,-1.55 1.55,1.55, height 0.8
SMA_RA-EDGE [mil]
  rrect50% 39.37x188 smd: 1(0,114)
  rect 80x188 smd: 2(-168,114) 2(168,114)
  rect 80x188 smd far side: 2(-168,114) 2(168,114)
  body extent -188,-375 187,187, height 172
SOT-23_5 [mil]
  rect 39x25 smd: 1(-50,37.5) 2(-50,0) 3(-50,-37.5) 4(50,-37.5) 5(50,37.5)
  silkscreen extent -20,-60 20,60, body extent -52,-60 51,60, height 39
TP-100_BLACK [mm]
  rect 1.7x1.7 hole 1.3: 1(0,0)
  body extent -1.25,-1.25 1.25,1.25, height 4.5
USB-C_RCP [mm] "CONN RCP USB3.1 TYPEC 24P SMD RA"
  rect 0.3x0.7 smd mask+0.051: A1(-3,3.085) A2(-2.5,3.085) A3(-2,3.085) A4(-1.5,3.085) A5(-1,3.085) A6(-0.5,3.085) A7(0.5,3.085) A8(1,3.085) A9(1.5,3.085) A10(2,3.085) A11(2.5,3.085) A12(3,3.085) B2(2.25,1.385) B3(1.75,1.385) B4(1.25,1.385) B5(0.75,1.385) B6(0.25,1.385) B7(-0.25,1.385) B8(-0.75,1.385) B9(-1.25,1.385) B10(-1.75,1.385) B11(-2.25,1.385)
  rect 0.9x0.7 smd mask+0.051: B1(3.05,1.385) B12(-3.05,1.385)
  oval 1.1x2.1 hole 0.6 slot 1.6 at 90 deg: SH1(-4.32,2.275) SH2(4.32,2.275)
  oval 1.1x3.6 hole 0.6 slot 2.1 at 90 deg copper offset 0,0.5: SH3(4.62,-3.085) SH4(-4.62,-3.085)
  silkscreen extent -3.76,3.65 -3.51,3.9, body extent -4.7,-5.04 4.69,3.26, height 3.7

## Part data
C1 C2 C4 C6: library part CAP0084, "Cap,100nF,10V,+/-10%,X7R,0402", Component Rating=X7R, Manufacturer 1=Kemet, Manufacturer Part Number 1=C0402C104K8RACTU, Package=0402, Supplier Part Number 1=399-3520-2-ND, Tolerance=10%, Voltage=10V
C3 C5: library part CAP0014, "CAP CER 10UF 10V 20% X5R 0402", Manufacturer 1=Samsung, Manufacturer Part Number 1=CL05A106MP8NUB8, Manufacturer Part Number 2=CL05A106MP5NUNC, Package=0402, Supplier Part Number 1=1276-6830-1-ND, Tolerance=20%, Voltage=10V
C7: library part CAP0023, "CAP CER 2.2UF 25V 20% X5R 0402", Component Rating=X5R, Manufacturer 1=Murata, Manufacturer Part Number 1=GRM155R61E225ME15D, Package=0402, Supplier Part Number 1=490-10457-1-ND, Tolerance=20%, Voltage=25V
C8 C9: library part CAP0049, "Update Later", Component Rating=DNF, Package=0402
C10 C11 C12 C13: library part CAP0164, "CAP CER 10UF 25V 20% X5R 0603", Component Rating=X5R, Manufacturer 1="Murata, Inc.", Manufacturer Part Number 1=GRM188R61E106MA73J, Package=0603, Supplier Part Number 1=490-12737-2-ND, Tolerance=20%, Voltage=25V
C14 C15: library part CAP0078, "Cap,1nF,50V,+/-10%,X7R,0402, RoHS", Component Rating=X7R, Manufacturer 1="Murata, Inc.", Manufacturer Part Number 1=GRM155R71H102KA01D, Package=0402, Supplier Part Number 1=490-1303-2-ND, Tolerance=10%, Voltage=50V
CN7: library part HDR0019, "Conn Straight Header 10x2 0.100\" 20 POS", Manufacturer 1="Molex/Waldom Electronics Corp", Manufacturer Part Number 1=90131-0130, Package=THRU-Hole, Supplier Part Number 1=WM50035-20-ND
CN8: library part HDR0015, "Conn Straight Header 8x2 0.100\" 16 POS", Manufacturer 1="Molex/Waldom Electronics Corp", Manufacturer Part Number 1=90131-0128, Package=THRU-Hole, Supplier Part Number 1=WM8126-ND
CN9: library part HDR0027, "Conn Straight Header 15x2 0.100\" 30 POS", Manufacturer 1="Molex/Waldom Electronics Corp", Manufacturer Part Number 1=90131-0135, Package=THRU-Hole, Supplier Part Number 1=WM8133-ND
CN10: library part HDR0029, "Conn Straight Header 17x2 0.100\" 32 POS", Manufacturer 1="Molex/Waldom Electronics Corp", Manufacturer Part Number 1=90131-0137, Package=THRU-Hole, Supplier Part Number 1="WM8134-ND (trimmed to length)"
D1 D2 D3: library part DIO0046, "LED GREEN 0402 SMD", Manufacturer 1=SunLED, Manufacturer Part Number 1=XZVGR68W-3, Package=0402, Supplier Part Number 1=1497-1386-2-ND, Voltage=2.0V
FID1 FID2 FID3: library part PAD0013, "1mm Round Fiducial, 0.5mm Space"
H1: library part HDR0098, "Conn Straight Header 2x1 0.100\" 2 POS (DNF)", Manufacturer 1=DNF, Package=THRU-Hole
H5 J1: library part HDR0012, "Conn Straight Header 5x2 0.100\" 10 POS", Manufacturer 1="Molex/Waldom Electronics Corp", Manufacturer Part Number 1=90131-0125, Package=THRU-Hole, Supplier Part Number 1=WM8123-ND
H6: library part HDR0090, "CONN,Vertical FTSH Series,0.05\"10 Pins, Through Hole", Manufacturer 1=Samtec, Manufacturer Part Number 1=FTSH-105-01-F-D-K, Package="FTSH 105D"
H11: library part HDR0006, "Conn Straight Header 2x1 0.100\" 2 POS", Manufacturer 1=Oupiin, Manufacturer Part Number 1=2011-1X02G00SB-1, Package=THRU-Hole, Supplier Part Number 1=2553-2011-1X02G00SB-1-ND
J2: library part CON0045, Manufacturer 1=Molex, Manufacturer Part Number 1=2012670005, Supplier Part Number 1=WM17992TR-ND
J3: library part CON0063, "CONN RCPT 8POS 0.1 GOLD PCB", Manufacturer 1="Amphenol FCI", Manufacturer Part Number 1=75915-308LF, Package=THRU-HOLE, Supplier Part Number 1=609-3559-ND
J4: library part CON0063, "CONN RCPT 8POS 0.1 GOLD PCB", Manufacturer 1="Amphenol FCI", Package=THRU-HOLE, Supplier Part Number 1=609-3559-ND
J5: library part CON0004, "Conn SMA Right Angel .187\" Female Socket", Manufacturer 1="Emerson Network", Manufacturer Part Number 1=142-0701-801, Package=SMA, Supplier Part Number 1=J502-ND
L1: library part IND0083, "BEAD 60OHMS 2500MA 32 MOHM", Current=2.5A, Manufacturer 1=Murata, Manufacturer Part Number 1=BLM15PX600SN1D, Package=0402, Resistance=32mOhm, Supplier Part Number 1=490-11023-1-ND
MH1 MH2 MH3 MH4 MH5: library part PAD0034, "MH NPTH 3.60mm DIA 3.20mm HOLE"
R1: library part RES0004, "RES SMD 1Kohm 1% 1/10W Thick film 0402", Manufacturer 1=Panasonic, Manufacturer Part Number 1=ERJ-2RKF1001X, Package=0402, Power=1/10W, Supplier Part Number 1=P1.00KLCT-ND, Tolerance=1%
R2 R3: library part RES0204, "RES SMD 3.9K OHM 1% 1/16W 0402", Manufacturer 1=Yageo, Manufacturer Part Number 1=RC0402FR-073K9L, Package=0402, Power=1/16W, Supplier Part Number 1=311-3.90KLRCT-ND, Tolerance=1%
R4 R5 R6 R7 R8 R9 R10 R11 R12 R13 R14 R15 R16 R18 R19 R23 R46: library part RES0002, "RES SMD 10Kohm 1% 1/10W Thick film 0402", Manufacturer 1=Panasonic, Manufacturer Part Number 1=ERJ-2RKF1002X, Package=0402, Power=1/10W, Supplier Part Number 1=P10.0KLCT-ND, Tolerance=1%
R17 R39 R52 R53 R74: library part RES0034, "Update Later", Package=0402, Power=DNF
R20 R24 R27 R35 R41 R56 R58 R59 R65 R72 R73: library part RES0119, "Res, 0 Ohm, 1/10W,+/-5%,0603 RoHS", Manufacturer 1=Rohm, Manufacturer 2=Yageo, Manufacturer Part Number 1=MCR03EZPJ000, Manufacturer Part Number 2=RC0603JR-070RL, Package=0603, Power=1/10W, Supplier Part Number 1=311-0.0GRCT-ND, Tolerance=5%
R21 R25 R28 R30 R33 R36 R43 R44 R45 R47 R57 R66 R67 R68 R69 R70 R71: library part RES0035, "Update Later", Package=0603, Power=DNF
R22 R26 R29 R31 R34 R37: library part RES0086, "Res, 47K Ohms,1/16W, 1%, 0402,SMD RoHS", Manufacturer 1=Rohm, Manufacturer 2=Yageo, Manufacturer Part Number 1=MCR01MZPF4702, Manufacturer Part Number 2=RC0402FR-0747KL, Package=0402, Power=1/16W, Supplier Part Number 1=311-47.0KLRCT-ND, Tolerance=1%
R38 R42 R48 R49: library part RES0001, "RES SMD 0ohm 1% 1/10W Thick film 0402", Manufacturer 1=Panasonic, Manufacturer Part Number 1=ERJ-2GE0R00X, Package=0402, Power=1/10W, Supplier Part Number 1=P0.0JCT-ND, Tolerance=1%
R40: library part RES0064, "Res, 220k Ohms, 1/16W, 1%, 0402,SMD", Manufacturer 1=Rohm, Manufacturer 2=Yageo, Manufacturer Part Number 1=MCR01MZPF2203, Manufacturer Part Number 2=RC0402FR-07220KL, Package=0402, Power=1/16W, Supplier Part Number 1=311-220KLRCT-ND, Tolerance=1%
R50 R51: library part RES0042, "Res, 1k Ohms, 1/16W, 1%, 0402,SMD", Manufacturer 1=Yageo, Manufacturer Part Number 1=RC0402FR-071KL, Package=0402, Power=1/16W, Supplier Part Number 1=311-1.00KLRTR-ND, Tolerance=1%
R54 R55: library part RES0043, "Res,10K Ohms,1/16W, 1%, 0402,SMD RoHS", Manufacturer 1=Rohm, Manufacturer 2=Yageo, Manufacturer Part Number 1=MCR01MZPF1002, Manufacturer Part Number 2=RC0402FR-0710KL, Package=0402, Power=1/16W, Supplier Part Number 1=311-10.0KLRCT-ND, Tolerance=1%
R60 R61: library part RES0094, "Res, 5.1K Ohms, 1/16W, 1%, 0402,SMD", Manufacturer 1=Rohm, Manufacturer 2=Yageo, Manufacturer Part Number 1=MCR01MZPF5101, Manufacturer Part Number 2=RC0402FR-075K1L, Package=0402, Power=1/16W, Supplier Part Number 1=311-5.10KLRCT-ND, Tolerance=1%
R62 R63 R64: library part RES0073, "Res, 330 Ohms, 1/16W, 1%, 0402,SMD", Manufacturer 1=Rohm, Manufacturer 2=Yageo, Manufacturer Part Number 1=MCR01MZPF3300, Manufacturer Part Number 2=RC0402FR-07330RL, Package=0402, Power=1/16W, Supplier Part Number 1=311-330LRCT-ND, Tolerance=1%
TP1 TP2: library part CON0001, "Test Point PCB, BLACK 0.040\"D", Manufacturer 1="Keystone Electronics", Manufacturer Part Number 1=5001, Package=THRU-Hole, Supplier Part Number 1=5001K-ND
U1: library part ICT0181, "IC EEPROM 32KBIT I2C SOT23-5", Manufacturer 1="Microchip Technology", Manufacturer Part Number 1=AT24C32D-STUM-T, Package=SOT23, Supplier Part Number 1=AT24C32D-STUM-TCT-ND
U2: library part MOD0007, "MM61xx-MF04", Manufacturer 1="Morse Micro"
U3: library part MOD0012, "MIKROBUS Module", Manufacturer 1=MIKROBUS, Manufacturer Part Number 1="MIKROBUS HOST"
U4 U5: library part REG0068, "IC REG LINEAR POS 3.0 2A 8LFCSP", Current=2A, Manufacturer 1="Analog Devices Inc.", Manufacturer Part Number 1=ADM7172ACPZ-3.0-R7, Package=PSON8, Supplier Part Number 1=ADM7172ACPZ-3.0-R7TR-ND, Voltage=3.0/ADJ
VS1: library part DIO0056, "TVS DIODE 6V 10.3V DO214AC", Current=38.8A, Manufacturer 1="Littelfuse Inc.", Manufacturer Part Number 1=SMAJ6.0A, Package=DO-214AC, Supplier Part Number 1=SMAJ6.0ALFCT-ND, Voltage=6V

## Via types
v1: diameter 23.62, hole 11.81, Top Layer to Bottom Layer, tented both sides, 296 vias

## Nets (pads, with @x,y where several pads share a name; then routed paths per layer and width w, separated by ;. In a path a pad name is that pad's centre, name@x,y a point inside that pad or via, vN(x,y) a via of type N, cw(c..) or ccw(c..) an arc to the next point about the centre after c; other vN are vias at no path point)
5V_USB: J2.A4 J2.A9 J2.B4 J2.B9 R58.1 R59.1 VS1.K | length 835.1
  Top Layer w12: 366.58,1517.74 366.58,1497.05 v1(366.63,1497) 366.63,1537.49 J2.A9@366.58,1537.54 366.58,1566.95 v1(371.5,1571.87) 376.42,1576.79 J2.B4@376.42,1604.47 376.42,1638.58 v1(375,1640) ; v1(475,1640) 474.84,1639.84 J2.B9@474.84,1604.47 474.94,1604.38 474.94,1575.69 v1(479.81,1570.82) 484.68,1565.95 J2.A4@484.68,1537.54 ; J2.A4@484.68,1529.76 484.68,1517.74 486.59,1515.84 486.59,1506.03 v1(488.81,1503.81)
  Top Layer w25: v1(390,1365) 410.37,1365 410.66,1365.29 426.41,1365.29 VS1.K@447.37,1386.25 ; v1(390,1400) 445.37,1400 VS1.K@447.37,1402 ; v1(390,1435) 426.41,1435 VS1.K@447.37,1414.04 ; v1(504.74,1365) 484.37,1365 484.08,1365.29 468.33,1365.29 VS1.K@447.37,1386.25 ; v1(504.74,1435) 468.33,1435 VS1.K@447.37,1414.04 ; R59.1@538.83,1406.59 R58.1@600.83,1406.59 ; R59.1@548.29,1405.85 545.05,1402.6 533,1402.6 530.4,1400 449.37,1400 VS1.K@447.37,1402 ; VS1.K@447.37,1386.25 VS1.K@447.37,1402 ; VS1.K@447.37,1386.25 VS1.K@447.37,1402 ; VS1.K@447.37,1402 VS1.K@447.37,1414.04
  other v1: 504.74,1400
CC1: J2.A5 R60.1 | length 168.2
  Top Layer w8: J2.A5@463.09,1535.64 J2.A5@465,1537.54 465,1490 485,1470 545.69,1470 R60.1@574.63,1470
CC2: J2.B5 R61.1 | length 379.1
  Top Layer w8: R61.1@217.63,1482 217.63,1602 279.44,1663.81 384.86,1663.81 398.81,1649.86 398.81,1630.14 396.1,1627.43 J2.B5@396.1,1604.47
EEPROM_SCL: CN9.19 R3.2 U1.1 | length 813.5
  Top Layer w8: U1.1@1586.13,470.63 1586.13,471.66 1594.63,480.16 R3.2@1638.63,480.16 1639.13,480.66 1639.13,508.5 v1(1639.63,509)
  Mid Layer 1 w8: v1(1639.63,509) 1779.63,649 1826.63,649 1850.63,673 1850.63,1052 1898.63,1100 CN9.19@1900,1100
EEPROM_SDA: CN9.21 R2.2 U1.3 | length 1066.7
  Top Layer w8: v1@1430.25,488 R2.2@1458.63,488 1460.5,486.13 1502.63,486.13 1511.13,477.63 U1.3@1511.13,470.63
  Bottom Layer w8: v1(1428.07,487.82) 1467.82,487.82 1750,770 1750,1124.45 1774.55,1149 1843.09,1149 1894.09,1200 CN9.21@1900,1200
